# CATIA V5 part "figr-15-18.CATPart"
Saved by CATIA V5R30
Part number: Part1
Bounding box of the stored display mesh (mm): x -46.56 to 46.56, y -38.965 to 25.965, z 0 to 40
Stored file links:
  D:\PROJECTS\CATIA V56R 2020\Resources\Parts File\c15_catia_v5_6r2020_prt\figr-15-18.CATPart
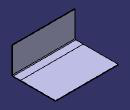
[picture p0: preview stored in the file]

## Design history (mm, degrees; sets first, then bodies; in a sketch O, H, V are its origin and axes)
SheetMetalParameters1: Thickness 1, BendRadius 1, KFactor 0.325257 {= log(min(100,max(20*SheetMetalParameters1.BendRadius,SheetMetalParameters1.Thickness)/SheetMetalParameters1.Thickness))/log(100)/2}, ReliefRadialLength 1, ReliefAxialLength 2, MinimumBendRadius 0
Body1 (main body)
  Sketch1 on xy-plane, origin (0, 0, 0), H (1, 0, 0), V (0, 1, 0)
    line L1 (-46.5596, 25.9646) -> (46.5596, 25.9646)
    line L2 (46.5596, 25.9646) -> (46.5596, -25.9646)
    line L3 (46.5596, -25.9646) -> (-46.5596, -25.9646)
    line L4 (-46.5596, -25.9646) -> (-46.5596, 25.9646)
    horizontal: L1 H, L3 H
    vertical: L2 V, L4 V
    symmetry: L1 L3 H, L4 L2 V
  Wall1: Thickness 1, Profile Sketch1
  d_NewWallOnEdge1: NewWallOnEdge_Edge edge [face of Wall1 | face of Wall1], NewWallOnEdge_Length 40, NewWallOnEdge_HeightLimitOffset 0, NewWallOnEdge_WidthOffset1 0, NewWallOnEdge_WidthOffset2 0, NewWallOnEdge_Angle 90, NewWallOnEdge_BendRadiusValue 1 {= SheetMetalParameters1.BendRadius}, NewWallOnEdge_BendTable SheetMetalParameters1, KFacteur 0.325257 {= log(min(100,max(20*d_NewWallOnEdge1.Radius,SheetMetalParameters1.Thickness)/SheetMetalParameters1.Thickness))/log(100)/2}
